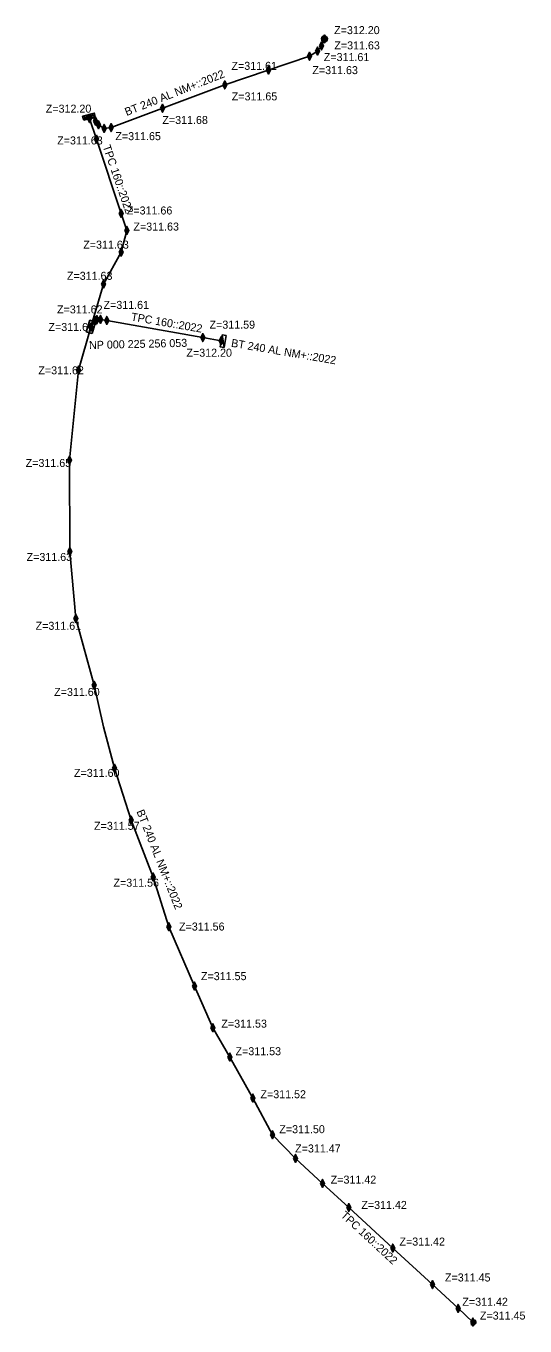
# Model space of a CAD drawing. Extents: x 799271 to 799523, y 67737 to 68184.
# Drawn here: x 799437 to 799461.9, y 68118.9 to 68183.9 of the extents above; entities that cross this region are included whole.
import ezdxf

# ---------------------------------------------------------------- set-up
doc = ezdxf.new("R2010")
doc.units = 0
for name, color, linetype in [('PGOC_BRCHT_LR_CONSTRUIT', 7, 'Continuous'), ('PGOC_BT_CONSTRUIT', 7, 'Continuous'), ('PGOC_PROTECTION_MECANIQUE', 7, 'Continuous'), ('PGOC_PTRL', 7, 'Continuous')]:
    doc.layers.add(name, color=color, linetype=linetype)

msp = doc.modelspace()

# ---------------------------------------------------------------- linework, layer by layer
at = {"layer": 'PGOC_BRCHT_LR_CONSTRUIT'}
msp.add_line((799446.886, 68167.837), (799446.787, 68168.461), dxfattribs=at)
msp.add_lwpolyline([(799440.231, 68168.853), (799440.453, 68169.171), (799440.529, 68169.221), (799440.713, 68169.236), (799441.019, 68169.182), (799445.818, 68168.329), (799446.737, 68168.165)], dxfattribs=at)
msp.add_lwpolyline([(799446.787, 68168.461), (799446.688, 68167.869), (799446.886, 68167.837), (799446.984, 68168.428)], close=True, dxfattribs=at)
at = {"layer": 'PGOC_BT_CONSTRUIT'}
for points in [[(799440.316, 68179.315), (799440.459, 68179.141), (799440.603, 68178.966), (799440.887, 68178.781), (799441.236, 68178.822), (799446.923, 68180.95), (799451.16, 68182.388), (799451.563, 68182.646), (799451.763, 68182.903), (799451.901, 68183.249)], [(799459.32, 68119.128), (799458.582, 68119.815), (799457.3, 68120.995), (799455.317, 68122.82), (799453.119, 68124.846), (799451.812, 68126.051), (799450.457, 68127.301), (799449.302, 68128.485), (799448.33, 68130.315), (799447.178, 68132.367), (799446.327, 68133.836), (799445.409, 68135.918), (799444.127, 68138.885), (799443.35, 68141.362), (799442.237, 68144.21), (799441.406, 68146.799), (799440.867, 68148.872), (799440.391, 68150.948), (799439.478, 68154.281), (799439.172, 68157.636), (799439.166, 68162.207), (799439.606, 68166.702), (799440.231, 68168.853), (799440.857, 68171.003), (799441.737, 68172.589), (799442.027, 68173.678), (799441.741, 68174.534), (799440.503, 68178.24), (799440.158, 68179.271), (799440.158, 68179.271)], [(799440.382, 68179.437), (799439.881, 68179.298)], [(799439.96, 68179.237), (799439.917, 68179.391)], [(799440.057, 68179.264), (799440.014, 68179.418)], [(799440.153, 68179.29), (799440.11, 68179.445)], [(799440.249, 68179.317), (799440.206, 68179.471)], [(799440.346, 68179.344), (799440.303, 68179.498)], [(799459.225, 68119.012), (799459.416, 68119.244)]]:
    msp.add_lwpolyline(points, dxfattribs=at)
for points in [[(799439.869, 68179.191), (799440.447, 68179.352), (799440.394, 68179.544), (799439.816, 68179.383)], [(799440.286, 68168.527), (799440.466, 68169.1), (799440.18, 68169.19), (799440, 68168.617)]]:
    msp.add_lwpolyline(points, close=True, dxfattribs=at)
msp.add_circle((799451.902, 68183.249), 0.15, dxfattribs=at)
msp.add_arc((799459.321, 68119.127), 0.15, 230.57483, 50.57483, dxfattribs=at)
at = {"layer": 'PGOC_PTRL'}
for points in [[(799451.663, 68182.903), (799451.763, 68183.103), (799451.863, 68182.903), (799451.763, 68182.703), (799451.663, 68182.903)], [(799451.763, 68183.103), (799451.763, 68182.703)], [(799451.801, 68183.249), (799451.901, 68183.449), (799452.001, 68183.249), (799451.901, 68183.049), (799451.801, 68183.249)], [(799452.001, 68183.249), (799451.901, 68183.249), (799451.801, 68183.249)], [(799451.901, 68183.449), (799451.901, 68183.049)], [(799451.06, 68182.388), (799451.16, 68182.588), (799451.26, 68182.388), (799451.16, 68182.188), (799451.06, 68182.388)], [(799451.26, 68182.388), (799451.16, 68182.388), (799451.06, 68182.388)], [(799451.16, 68182.588), (799451.16, 68182.188)], [(799451.463, 68182.646), (799451.563, 68182.846), (799451.663, 68182.646), (799451.563, 68182.446), (799451.463, 68182.646)], [(799451.663, 68182.646), (799451.563, 68182.646), (799451.463, 68182.646)], [(799451.563, 68182.846), (799451.563, 68182.446)], [(799451.863, 68182.903), (799451.763, 68182.903), (799451.663, 68182.903)], [(799449.008, 68181.691), (799449.108, 68181.891), (799449.208, 68181.691), (799449.108, 68181.491), (799449.008, 68181.691)], [(799449.108, 68181.891), (799449.108, 68181.491)], [(799446.823, 68180.95), (799446.923, 68181.15), (799447.023, 68180.95), (799446.923, 68180.75), (799446.823, 68180.95)], [(799446.923, 68181.15), (799446.923, 68180.75)], [(799449.208, 68181.691), (799449.108, 68181.691), (799449.008, 68181.691)], [(799447.023, 68180.95), (799446.923, 68180.95), (799446.823, 68180.95)], [(799443.711, 68179.785), (799443.811, 68179.985), (799443.911, 68179.785), (799443.811, 68179.585), (799443.711, 68179.785)], [(799443.911, 68179.785), (799443.811, 68179.785), (799443.711, 68179.785)], [(799443.811, 68179.985), (799443.811, 68179.585)], [(799440.058, 68179.271), (799440.158, 68179.471), (799440.258, 68179.271), (799440.158, 68179.071), (799440.058, 68179.271)], [(799440.258, 68179.271), (799440.158, 68179.271), (799440.058, 68179.271)], [(799440.158, 68179.471), (799440.158, 68179.071)], [(799440.359, 68179.141), (799440.459, 68179.341), (799440.559, 68179.141), (799440.459, 68178.941), (799440.359, 68179.141)], [(799440.559, 68179.141), (799440.459, 68179.141), (799440.359, 68179.141)], [(799440.459, 68179.341), (799440.459, 68178.941)], [(799440.503, 68178.966), (799440.603, 68179.166), (799440.703, 68178.966), (799440.603, 68178.766), (799440.503, 68178.966)], [(799440.603, 68179.166), (799440.603, 68178.766)], [(799440.703, 68178.966), (799440.603, 68178.966), (799440.503, 68178.966)], [(799440.787, 68178.781), (799440.887, 68178.981), (799440.987, 68178.781), (799440.887, 68178.581), (799440.787, 68178.781)], [(799440.987, 68178.781), (799440.887, 68178.781), (799440.787, 68178.781)], [(799440.887, 68178.981), (799440.887, 68178.581)], [(799441.136, 68178.822), (799441.236, 68179.022), (799441.336, 68178.822), (799441.236, 68178.622), (799441.136, 68178.822)], [(799441.336, 68178.822), (799441.236, 68178.822), (799441.136, 68178.822)], [(799441.236, 68179.022), (799441.236, 68178.622)], [(799440.403, 68178.24), (799440.503, 68178.44), (799440.603, 68178.24), (799440.503, 68178.04), (799440.403, 68178.24)], [(799440.603, 68178.24), (799440.503, 68178.24), (799440.403, 68178.24)], [(799440.503, 68178.44), (799440.503, 68178.04)], [(799441.641, 68174.534), (799441.741, 68174.734), (799441.841, 68174.534), (799441.741, 68174.334), (799441.641, 68174.534)], [(799441.741, 68174.734), (799441.741, 68174.334)], [(799441.841, 68174.534), (799441.741, 68174.534), (799441.641, 68174.534)], [(799441.927, 68173.678), (799442.027, 68173.878), (799442.127, 68173.678), (799442.027, 68173.478), (799441.927, 68173.678)], [(799442.127, 68173.678), (799442.027, 68173.678), (799441.927, 68173.678)], [(799442.027, 68173.878), (799442.027, 68173.478)], [(799441.637, 68172.589), (799441.737, 68172.789), (799441.837, 68172.589), (799441.737, 68172.389), (799441.637, 68172.589)], [(799441.737, 68172.789), (799441.737, 68172.389)], [(799441.837, 68172.589), (799441.737, 68172.589), (799441.637, 68172.589)], [(799440.757, 68171.003), (799440.857, 68171.203), (799440.957, 68171.003), (799440.857, 68170.803), (799440.757, 68171.003)], [(799440.957, 68171.003), (799440.857, 68171.003), (799440.757, 68171.003)], [(799440.857, 68171.203), (799440.857, 68170.803)], [(799440.353, 68169.171), (799440.453, 68169.371), (799440.553, 68169.171), (799440.453, 68168.971), (799440.353, 68169.171)], [(799440.429, 68169.221), (799440.529, 68169.421), (799440.629, 68169.221), (799440.529, 68169.021), (799440.429, 68169.221)], [(799440.453, 68169.371), (799440.453, 68168.971)], [(799440.529, 68169.421), (799440.529, 68169.021)], [(799440.613, 68169.236), (799440.713, 68169.436), (799440.813, 68169.236), (799440.713, 68169.036), (799440.613, 68169.236)], [(799440.713, 68169.436), (799440.713, 68169.036)], [(799440.919, 68169.182), (799441.019, 68169.382), (799441.119, 68169.182), (799441.019, 68168.982), (799440.919, 68169.182)], [(799441.019, 68169.382), (799441.019, 68168.982)], [(799440.131, 68168.853), (799440.231, 68169.053), (799440.331, 68168.853), (799440.231, 68168.653), (799440.131, 68168.853)], [(799440.331, 68168.853), (799440.231, 68168.853), (799440.131, 68168.853)], [(799440.231, 68169.053), (799440.231, 68168.653)], [(799440.553, 68169.171), (799440.453, 68169.171), (799440.353, 68169.171)], [(799440.629, 68169.221), (799440.529, 68169.221), (799440.429, 68169.221)], [(799440.813, 68169.236), (799440.713, 68169.236), (799440.613, 68169.236)], [(799441.119, 68169.182), (799441.019, 68169.182), (799440.919, 68169.182)], [(799445.718, 68168.329), (799445.818, 68168.529), (799445.918, 68168.329), (799445.818, 68168.129), (799445.718, 68168.329)], [(799445.918, 68168.329), (799445.818, 68168.329), (799445.718, 68168.329)], [(799445.818, 68168.529), (799445.818, 68168.129)], [(799446.637, 68168.165), (799446.737, 68168.365), (799446.837, 68168.165), (799446.737, 68167.965), (799446.637, 68168.165)], [(799446.837, 68168.165), (799446.737, 68168.165), (799446.637, 68168.165)], [(799446.737, 68168.365), (799446.737, 68167.965)], [(799439.506, 68166.702), (799439.606, 68166.902), (799439.706, 68166.702), (799439.606, 68166.502), (799439.506, 68166.702)], [(799439.606, 68166.902), (799439.606, 68166.502)], [(799439.706, 68166.702), (799439.606, 68166.702), (799439.506, 68166.702)], [(799439.066, 68162.207), (799439.166, 68162.407), (799439.266, 68162.207), (799439.166, 68162.007), (799439.066, 68162.207)], [(799439.266, 68162.207), (799439.166, 68162.207), (799439.066, 68162.207)], [(799439.166, 68162.407), (799439.166, 68162.007)], [(799439.072, 68157.636), (799439.172, 68157.836), (799439.272, 68157.636), (799439.172, 68157.436), (799439.072, 68157.636)], [(799439.172, 68157.836), (799439.172, 68157.436)], [(799439.272, 68157.636), (799439.172, 68157.636), (799439.072, 68157.636)], [(799439.378, 68154.281), (799439.478, 68154.481), (799439.578, 68154.281), (799439.478, 68154.081), (799439.378, 68154.281)], [(799439.478, 68154.481), (799439.478, 68154.081)], [(799439.578, 68154.281), (799439.478, 68154.281), (799439.378, 68154.281)], [(799440.291, 68150.948), (799440.391, 68151.148), (799440.491, 68150.948), (799440.391, 68150.748), (799440.291, 68150.948)], [(799440.491, 68150.948), (799440.391, 68150.948), (799440.291, 68150.948)], [(799440.391, 68151.148), (799440.391, 68150.748)], [(799441.306, 68146.799), (799441.406, 68146.999), (799441.506, 68146.799), (799441.406, 68146.599), (799441.306, 68146.799)], [(799441.506, 68146.799), (799441.406, 68146.799), (799441.306, 68146.799)], [(799441.406, 68146.999), (799441.406, 68146.599)], [(799442.137, 68144.21), (799442.237, 68144.41), (799442.337, 68144.21), (799442.237, 68144.01), (799442.137, 68144.21)], [(799442.337, 68144.21), (799442.237, 68144.21), (799442.137, 68144.21)], [(799442.237, 68144.41), (799442.237, 68144.01)], [(799443.25, 68141.362), (799443.35, 68141.562), (799443.45, 68141.362), (799443.35, 68141.162), (799443.25, 68141.362)], [(799443.35, 68141.562), (799443.35, 68141.162)], [(799443.45, 68141.362), (799443.35, 68141.362), (799443.25, 68141.362)], [(799444.027, 68138.885), (799444.127, 68139.085), (799444.227, 68138.885), (799444.127, 68138.685), (799444.027, 68138.885)], [(799444.227, 68138.885), (799444.127, 68138.885), (799444.027, 68138.885)], [(799444.127, 68139.085), (799444.127, 68138.685)], [(799445.309, 68135.918), (799445.409, 68136.118), (799445.509, 68135.918), (799445.409, 68135.718), (799445.309, 68135.918)], [(799445.509, 68135.918), (799445.409, 68135.918), (799445.309, 68135.918)], [(799445.409, 68136.118), (799445.409, 68135.718)], [(799446.227, 68133.836), (799446.327, 68134.036), (799446.427, 68133.836), (799446.327, 68133.636), (799446.227, 68133.836)], [(799446.427, 68133.836), (799446.327, 68133.836), (799446.227, 68133.836)], [(799446.327, 68134.036), (799446.327, 68133.636)], [(799447.078, 68132.367), (799447.178, 68132.567), (799447.278, 68132.367), (799447.178, 68132.167), (799447.078, 68132.367)], [(799447.278, 68132.367), (799447.178, 68132.367), (799447.078, 68132.367)], [(799447.178, 68132.567), (799447.178, 68132.167)], [(799448.23, 68130.315), (799448.33, 68130.515), (799448.43, 68130.315), (799448.33, 68130.115), (799448.23, 68130.315)], [(799448.33, 68130.515), (799448.33, 68130.115)], [(799448.43, 68130.315), (799448.33, 68130.315), (799448.23, 68130.315)], [(799449.202, 68128.485), (799449.302, 68128.685), (799449.402, 68128.485), (799449.302, 68128.285), (799449.202, 68128.485)], [(799449.402, 68128.485), (799449.302, 68128.485), (799449.202, 68128.485)], [(799449.302, 68128.685), (799449.302, 68128.285)], [(799450.357, 68127.301), (799450.457, 68127.501), (799450.557, 68127.301), (799450.457, 68127.101), (799450.357, 68127.301)], [(799450.557, 68127.301), (799450.457, 68127.301), (799450.357, 68127.301)], [(799450.457, 68127.501), (799450.457, 68127.101)], [(799451.712, 68126.051), (799451.812, 68126.251), (799451.912, 68126.051), (799451.812, 68125.851), (799451.712, 68126.051)], [(799451.912, 68126.051), (799451.812, 68126.051), (799451.712, 68126.051)], [(799451.812, 68126.251), (799451.812, 68125.851)], [(799453.019, 68124.846), (799453.119, 68125.046), (799453.219, 68124.846), (799453.119, 68124.646), (799453.019, 68124.846)], [(799453.219, 68124.846), (799453.119, 68124.846), (799453.019, 68124.846)], [(799453.119, 68125.046), (799453.119, 68124.646)], [(799455.217, 68122.82), (799455.317, 68123.02), (799455.417, 68122.82), (799455.317, 68122.62), (799455.217, 68122.82)], [(799455.417, 68122.82), (799455.317, 68122.82), (799455.217, 68122.82)], [(799455.317, 68123.02), (799455.317, 68122.62)], [(799457.2, 68120.995), (799457.3, 68121.195), (799457.4, 68120.995), (799457.3, 68120.795), (799457.2, 68120.995)], [(799457.4, 68120.995), (799457.3, 68120.995), (799457.2, 68120.995)], [(799457.3, 68121.195), (799457.3, 68120.795)], [(799458.482, 68119.809), (799458.582, 68120.009), (799458.682, 68119.809), (799458.582, 68119.609), (799458.482, 68119.809)], [(799458.582, 68120.009), (799458.582, 68119.609)], [(799458.682, 68119.809), (799458.582, 68119.809), (799458.482, 68119.809)], [(799459.22, 68119.128), (799459.32, 68119.328), (799459.42, 68119.128), (799459.32, 68118.928), (799459.22, 68119.128)], [(799459.32, 68119.328), (799459.32, 68118.928)], [(799459.42, 68119.128), (799459.32, 68119.128), (799459.22, 68119.128)]]:
    msp.add_lwpolyline(points, dxfattribs=at)

# ---------------------------------------------------------------- texts
at = {"layer": 'PGOC_BRCHT_LR_CONSTRUIT'}
msp.add_text('BT 240 AL NM+::2022', height=0.4, rotation=350.40405, dxfattribs=at).set_placement((799447.218, 68167.871))
at = {"layer": 'PGOC_BT_CONSTRUIT'}
for s, rotation, p in [('BT 240 AL NM+::2022', 21.59842, (799442.016, 68179.397)), ('NP 000 225 256 053', 1.35034, (799440.14, 68167.751)), ('BT 240 AL NM+::2022', 291.59842, (799442.499, 68144.644))]:
    msp.add_text(s, height=0.4, rotation=rotation, dxfattribs=at).set_placement(p)
at = {"layer": 'PGOC_PROTECTION_MECANIQUE'}
for rotation, p in [(288.97578, (799440.815, 68177.877)), (350.17329, (799442.216, 68169.182)), (317.20229, (799452.684, 68124.415))]:
    msp.add_text('TPC 160::2022', height=0.4, rotation=rotation, dxfattribs=at).set_placement(p)
at = {"layer": 'PGOC_PTRL'}
for s, p in [('Z=312.20', (799452.387, 68183.491)), ('Z=311.63', (799452.395, 68182.729)), ('Z=311.61', (799451.87, 68182.145)), ('Z=311.61', (799447.255, 68181.706)), ('Z=311.63', (799451.299, 68181.492)), ('Z=311.65', (799447.27, 68180.18)), ('Z=312.20', (799437.975, 68179.567)), ('Z=311.68', (799443.801, 68179.001)), ('Z=311.65', (799441.453, 68178.192)), ('Z=311.63', (799438.545, 68177.978)), ('Z=311.66', (799442.024, 68174.478)), ('Z=311.63', (799442.356, 68173.673)), ('Z=311.63', (799439.847, 68172.769)), ('Z=311.63', (799439.032, 68171.212)), ('Z=311.61', (799440.86, 68169.759)), ('Z=311.62', (799438.537, 68169.535)), ('Z=311.61', (799438.108, 68168.655)), ('Z=311.59', (799446.159, 68168.772)), ('Z=312.20', (799445.005, 68167.37)), ('Z=311.62', (799437.603, 68166.49)), ('Z=311.65', (799436.969, 68161.86)), ('Z=311.63', (799437.016, 68157.162)), ('Z=311.61', (799437.466, 68153.722)), ('Z=311.60', (799438.393, 68150.416)), ('Z=311.60', (799439.384, 68146.37)), ('Z=311.57', (799440.389, 68143.726)), ('Z=311.56', (799441.357, 68140.882)), ('Z=311.56', (799444.634, 68138.691)), ('Z=311.55', (799445.73, 68136.213)), ('Z=311.53', (799446.751, 68133.84)), ('Z=311.53', (799447.458, 68132.461)), ('Z=311.52', (799448.704, 68130.312)), ('Z=311.50', (799449.646, 68128.564)), ('Z=311.47', (799450.437, 68127.601)), ('Z=311.42', (799452.215, 68126.044)), ('Z=311.42', (799453.745, 68124.778)), ('Z=311.42', (799455.651, 68122.948)), ('Z=311.45', (799457.925, 68121.154)), ('Z=311.42', (799458.795, 68119.941)), ('Z=311.45', (799459.673, 68119.25))]:
    msp.add_text(s, height=0.4, dxfattribs=at).set_placement(p)

doc.saveas('drawing.dxf')
